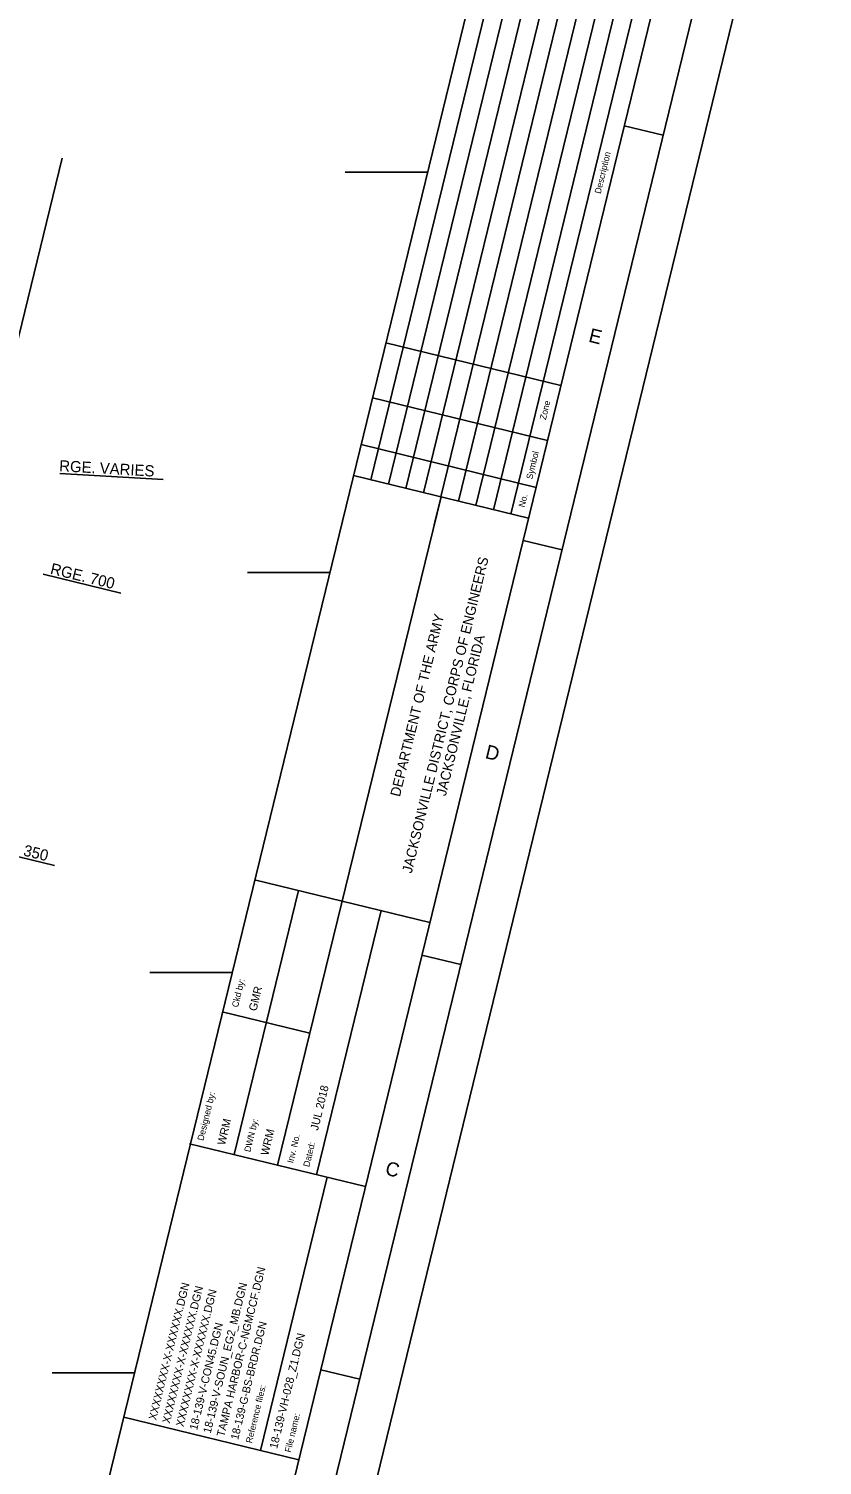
# Model space of a CAD drawing. Extents: x 412170 to 417250, y 1187847 to 1192192.
# Drawn here: x 416259 to 417250, y 1188884 to 1190679 of the extents above; entities that cross this region are included whole.
import ezdxf

# ---------------------------------------------------------------- set-up
doc = ezdxf.new("R2010")
doc.units = 0
for name, color, linetype in [('G-ANNO-NPLT', 7, 'Continuous'), ('G-ANNO-TEXT-DRWG', 7, 'Continuous'), ('G-ANNO-TEXT-PROJ', 7, 'Continuous'), ('G-ANNO-TEXT-TTLB', 7, 'Continuous'), ('G-ANNO-TTLB', 7, 'Continuous'), ('V-ALGN-TEXT', 7, 'Continuous'), ('V-ANNO-MATC', 7, 'Continuous'), ('V-TOPO-COOR-STAT', 7, 'Continuous')]:
    doc.layers.add(name, color=color, linetype=linetype)

msp = doc.modelspace()

# ---------------------------------------------------------------- linework, layer by layer
at = {"layer": 'G-ANNO-NPLT'}
msp.add_lwpolyline([(412975.1, 1192192.3), (417249.8, 1191149.8), (416444.2, 1187846.7), (412169.5, 1188889.2)], close=True, dxfattribs=at)
at = {"layer": 'G-ANNO-TTLB'}
for p, q in [((416910.3, 1191129.7), (416152.1, 1188020.8)), ((416884.5, 1190929.7), (416686, 1190115.7)), ((416906.4, 1190924.4), (416707.9, 1190110.4)), ((416928.2, 1190919.1), (416729.7, 1190105)), ((416950.1, 1190913.8), (416751.6, 1190099.7)), ((416972, 1190908.4), (416773.4, 1190094.4)), ((416993.8, 1190903.1), (416795.3, 1190089)), ((417015.7, 1190897.8), (416817.2, 1190083.7)), ((417037.5, 1190892.4), (416839, 1190078.4)), ((417059.4, 1190887.1), (416860.9, 1190073)), ((417051.1, 1190546.2), (417002.5, 1190558.1)), ((416704.8, 1190287.1), (416923.4, 1190233.8)), ((416688, 1190218), (416906.6, 1190164.7)), ((416673.8, 1190159.7), (416892.4, 1190106.3)), ((416664.3, 1190121), (416882.9, 1190067.7)), ((416569.3, 1189259.4), (416773.6, 1190094.3)), ((416773.6, 1190094.3), (416765.2, 1190059.9)), ((416924.7, 1190028.1), (416876.2, 1190040)), ((416540.4, 1189616.1), (416759.7, 1189562.6)), ((416515, 1189272.7), (416595.7, 1189602.6)), ((416698.6, 1189577.5), (416618.1, 1189247.5)), ((416798.4, 1189510), (416749.8, 1189521.8)), ((416500.1, 1189451.1), (416609.7, 1189424.3)), ((416459.5, 1189286.2), (416679.3, 1189232.6)), ((416631.4, 1189244.3), (416548.1, 1188902.9)), ((416672, 1188991.9), (416623.4, 1189003.7)), ((416377.4, 1188944.5), (416596, 1188891.2))]:
    msp.add_line(p, q, dxfattribs=at)
for points in [[(412229.9, 1188925.9), (416407.5, 1187907.1), (417189.3, 1191113.1), (413011.8, 1192131.9)], [(417128.9, 1191076.4), (413121.4, 1192053.7), (412363.2, 1188944.8), (416370.7, 1187967.5)]]:
    msp.add_lwpolyline(points, close=True, dxfattribs=at)
at = {"layer": 'V-ALGN-TEXT'}
for p, q in [((416297.5, 1190123.7), (416426.5, 1190116.3)), ((416276.4, 1189997.7), (416373.6, 1189974)), ((416193.5, 1189657.6), (416290.6, 1189633.9))]:
    msp.add_line(p, q, dxfattribs=at)
at = {"layer": 'V-ANNO-MATC'}
msp.add_line((416300.3, 1190517.6), (415930.5, 1189001.2), dxfattribs=at)
at = {"layer": 'V-TOPO-COOR-STAT'}
for p, q in [((416653.8, 1190500), (416756.7, 1190500)), ((416531.9, 1190000), (416634.8, 1190000)), ((416409.9, 1189500), (416512.9, 1189500)), ((416288, 1189000), (416390.9, 1189000))]:
    msp.add_line(p, q, dxfattribs=at)

# ---------------------------------------------------------------- texts
at = {"layer": 'G-ANNO-TEXT-DRWG'}
for s, p in [('GMR', (416542.9, 1189451.3)), ('WRM', (416503.6, 1189283.7)), ('WRM', (416557.7, 1189270.8)), ('TAMPA HARBOR-C-NGMCCF.DGN', (416502.8, 1188919.4)), ('XXXXXXXX-X-XXXXXX.DGN', (416417.8, 1188940.2)), ('XXXXXXXX-X-XXXXXX.DGN', (416434.8, 1188936)), ('18-139-V-SOUN_EG2_MB.DGN', (416485.8, 1188923.6)), ('XXXXXXXX-X-XXXXXX.DGN', (416451.8, 1188931.9)), ('18-139-V-CON45.DGN', (416468.8, 1188927.7)), ('18-139-VH-028_Z1.DGN', (416568.8, 1188904.4))]:
    msp.add_text(s, height=10, rotation=76.2946, dxfattribs=at).set_placement(p)
at = {"layer": 'G-ANNO-TEXT-PROJ'}
for s, height, p in [('JUL 2018', 10, (416619.8, 1189302.2)), ('18-139-G-BS-BRDR.DGN', 9.8, (416520.1, 1188915.6))]:
    msp.add_text(s, height=height, rotation=76.2946, dxfattribs=at).set_placement(p)
at = {"layer": 'G-ANNO-TEXT-TTLB'}
for s, height, p in [('Description', 8, (416973, 1190472.6)), ('Zone', 8, (416904.5, 1190190.1)), ('Symbol', 8, (416887.5, 1190115.7)), ('No.', 8, (416878, 1190080.8)), ('JACKSONVILLE DISTRICT, CORPS OF ENGINEERS', 12.5, (416736.9, 1189623.4)), ('DEPARTMENT OF THE ARMY', 12.5, (416722.1, 1189719)), ('JACKSONVILLE, FLORIDA', 12.5, (416779.5, 1189719.9)), ('Ckd by:', 8, (416519.9, 1189456)), ('Designed by:', 8, (416476.8, 1189289.4)), ('DWN by:', 8, (416535.3, 1189275.2)), ('Inv. No.', 8, (416588.8, 1189261.4)), ('Dated:', 8, (416609, 1189256.6)), ('Reference files:', 8, (416537.3, 1188911.5)), ('File name:', 8, (416585.9, 1188899.9))]:
    msp.add_text(s, height=height, rotation=76.2946, dxfattribs=at).set_placement(p)
at = {"layer": 'G-ANNO-TTLB'}
for s, p in [('E', (416956.9, 1190288.5)), ('D', (416827.7, 1189768.2)), ('C', (416702.8, 1189247.8))]:
    msp.add_text(s, height=17.5, rotation=346.2946, dxfattribs=at).set_placement(p)
at = {"layer": 'V-ALGN-TEXT'}
for s, rotation, p in [('RGE. VARIES', 356.7498, (416296.4, 1190126.5)), ('RGE. 700', 346.2946, (416284.6, 1189998.5)), ('RGE. 350', 346.2946, (416201.7, 1189658.5))]:
    msp.add_text(s, height=13.92, rotation=rotation, dxfattribs=at).set_placement(p)

doc.saveas('drawing.dxf')
